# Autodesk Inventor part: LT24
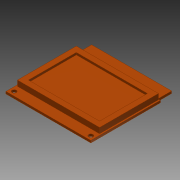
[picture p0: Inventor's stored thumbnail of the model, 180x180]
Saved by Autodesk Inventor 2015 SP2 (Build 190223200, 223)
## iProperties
Created: 2015-08
Part Number: LT24
Material: Phenolharz
Document SubType Name: Modeling
Designer: rYan
Mass: 18.4313 g
Surface Area: 89.6256 cm^2
Volume: 13.356 cm^3
Density: 1.38 g/cm^3
Appearance: Glatt - hellorange
Author: rYan
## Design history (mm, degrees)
sketch "Skizze1"
  geometry: L1 (-29.2, 4.2)-(29.2, 4.2); L2 (29.2, 4.2)-(29.2, -5.8); L3 (29.2, -5.8)-(31, -5.8); L4 (31, -5.8)-(31, -56.6); L5 (31, -56.6)-(-31, -56.6); L6 (-31, -56.6)-(-31, -5.8); L7 (-31, -5.8)-(-29.2, -5.8); L8 (-29.2, -5.8)-(-29.2, 4.2); L9 (-43.4, 0)-(43.4, 0) reference; L10 (0, 16.36)-(0, -68.76) reference; 1 further point
  constraints: 16 end point, 6 perpendicular, 1 horizontal, 1 vertical, 3 other
  dimensions: "d0" = 4.2 distance between parallel lines of L1 L9; "d1" = 5.8 distance between parallel lines of L9 L7; "d2" = 56.6 distance between parallel lines of L5 L9; "d3" = 62 distance of L4.end L5.end; "d4" = 58.4 distance of L1.start L1.end
extrude "Extrusion1" new body sketch "Skizze1" distance "d5" = 1.6; taper "d6" = 0 deg
sketch "Skizze2"
  geometry: L1 (-28, -53.6)-(28, -53.6); L2 (0, 16.36)-(0, -68.76) reference; L3 (-43.4, 0)-(43.4, 0) reference; 1 further point
  constraints: 2 end point, 1 horizontal, 1 symmetric about line
  dimensions: "d7" = 53.6 distance between parallel lines of L1 L3; "d8" = 56 distance of L1.start L1.end
hole "Bohrung1" sketch "Skizze2" at (-28, -53.6), (28, -53.6) diameter "d9" = 3.2; stored, may be unused: countersink angle "d13" = 90 deg, drill point angle "d15" = 118 deg; dims "d10" = 6, "d11" = 4, "d12" = 2, "d14" = 8
sketch "Skizze3"
  geometry: L1 (0, 16.36)-(0, -68.76) reference; L2 (-43.4, 0)-(43.4, 0) reference; L3 (-30, -6.2)-(30, -6.2); L4 (30, -6.2)-(30, -49.2); L5 (30, -49.2)-(-30, -49.2); L6 (-30, -49.2)-(-30, -6.2); 1 further point
  constraints: 8 end point, 2 parallel, 1 horizontal, 1 perpendicular, 1 other
  dimensions: "d16" = 60 distance of L3.start L3.end; "d17" = 43 distance of L5.end L3.start; "d18" = 6.2 distance between parallel lines of L2 L3
extrude "Extrusion2" join sketch "Skizze3" distance "d19" = 4; taper "d20" = 0 deg
feature "Wandung1" dims "d21" = 4
node "Volumenkörper1"
